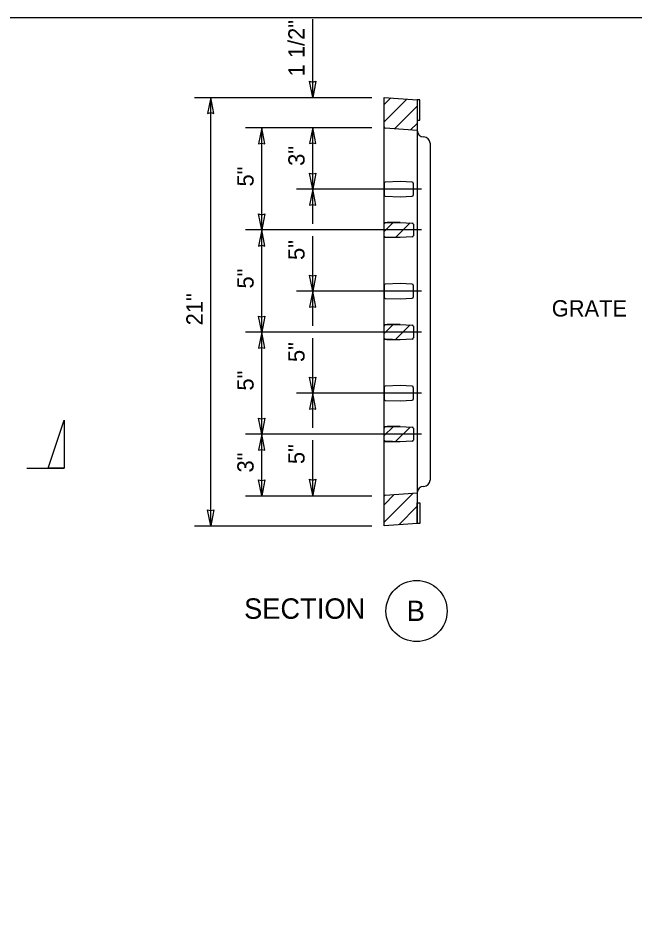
# Model space of a CAD drawing. Extents: x 99862 to 103151, y 100000 to 102076.
# Drawn here: x 100524 to 101128, y 101197 to 102076 of the extents above; entities that cross this region are included whole.
import ezdxf

# ---------------------------------------------------------------- set-up
doc = ezdxf.new("R2010")
doc.units = 0
for name, color, linetype in [('Level 1', 7, 'Continuous'), ('Level 11', 7, 'Continuous'), ('Level 15', 7, 'Continuous'), ('Level 17', 7, 'Continuous'), ('Level 2', 7, 'Continuous'), ('Level 20', 7, 'Continuous'), ('Level 9', 7, 'Continuous')]:
    doc.layers.add(name, color=color, linetype=linetype)

msp = doc.modelspace()

# ---------------------------------------------------------------- linework, layer by layer
at = {"layer": 'Level 1'}
for p, q in [((100882.87, 101606.72), (100882.87, 101968.65)), ((100927.87, 101952.68), (100927.87, 101622.68))]:
    msp.add_line(p, q, dxfattribs=at)
msp.add_lwpolyline([(99862, 99999.5), (103151, 99999.5), (103151, 102075.5), (99862, 102075.5)], close=True, dxfattribs=at)
for centre, start, end in [((100921.62, 101965.18), 180, 270), ((100921.62, 101952.68), 0, 90), ((100921.62, 101622.68), 270, 0), ((100921.62, 101610.18), 90, 180)]:
    msp.add_arc(centre, 6.25, start, end, dxfattribs=at)
at = {"layer": 'Level 11'}
for points in [[(100917.87, 101995.18), (100915.37, 101995.18), (100915.37, 101975.18), (100917.87, 101975.18)], [(100917.87, 101580.18), (100915.37, 101580.18), (100915.37, 101600.18), (100917.87, 101600.18)]]:
    msp.add_lwpolyline(points, close=True, dxfattribs=at)
at = {"layer": 'Level 15'}
for p, q in [((100812.87, 101997.68), (100812.87, 102074.17)), ((100696.87, 101997.68), (100870.87, 101997.68)), ((100712.87, 101577.68), (100712.87, 101997.68)), ((100746.87, 101968.17), (100870.87, 101968.17)), ((100762.87, 101867.69), (100762.87, 101967.68)), ((100812.87, 101907.69), (100812.87, 101968.17)), ((100919.52, 101907.69), (100796.87, 101907.69)), ((100812.87, 101873.69), (100812.87, 101907.69)), ((100919.52, 101867.69), (100746.87, 101867.69)), ((100762.87, 101767.69), (100762.87, 101867.69)), ((100812.87, 101807.69), (100812.87, 101861.69)), ((100919.52, 101807.69), (100796.87, 101807.69)), ((100812.87, 101773.69), (100812.87, 101807.69)), ((100919.52, 101767.69), (100746.87, 101767.69)), ((100762.87, 101667.69), (100762.87, 101767.69)), ((100812.87, 101707.69), (100812.87, 101761.69)), ((100919.52, 101707.69), (100796.87, 101707.69)), ((100812.87, 101673.69), (100812.87, 101707.69)), ((100919.52, 101667.69), (100746.87, 101667.69)), ((100762.87, 101607.21), (100762.87, 101667.69)), ((100812.87, 101607.69), (100812.87, 101661.69)), ((100746.87, 101607.21), (100870.87, 101607.21)), ((100696.87, 101577.68), (100870.87, 101577.68))]:
    msp.add_line(p, q, dxfattribs=at)
for points in [[(100812.87, 101997.68), (100809.78, 102013.41), (100812.87, 102012.68), (100815.95, 102013.41)], [(100712.87, 101997.68), (100709.78, 101981.96), (100712.87, 101982.69), (100715.95, 101981.96)], [(100762.87, 101967.68), (100759.78, 101951.96), (100762.87, 101952.69), (100765.95, 101951.96)], [(100812.87, 101968.17), (100809.78, 101952.44), (100812.87, 101953.17), (100815.95, 101952.44)], [(100812.87, 101907.69), (100809.78, 101923.41), (100812.87, 101922.68), (100815.95, 101923.41)], [(100812.87, 101907.69), (100809.78, 101891.96), (100812.87, 101892.69), (100815.95, 101891.96)], [(100762.87, 101867.69), (100759.78, 101883.41), (100762.87, 101882.68), (100765.95, 101883.41)], [(100762.87, 101867.69), (100759.78, 101851.96), (100762.87, 101852.69), (100765.95, 101851.96)], [(100812.87, 101807.69), (100809.78, 101823.41), (100812.87, 101822.68), (100815.95, 101823.41)], [(100812.87, 101807.69), (100809.78, 101791.96), (100812.87, 101792.69), (100815.95, 101791.96)], [(100762.87, 101767.69), (100759.78, 101783.41), (100762.87, 101782.68), (100765.95, 101783.41)], [(100762.87, 101767.69), (100759.78, 101751.96), (100762.87, 101752.69), (100765.95, 101751.96)], [(100812.87, 101707.69), (100809.78, 101723.41), (100812.87, 101722.68), (100815.95, 101723.41)], [(100812.87, 101707.69), (100809.78, 101691.96), (100812.87, 101692.69), (100815.95, 101691.96)], [(100762.87, 101667.69), (100759.78, 101683.41), (100762.87, 101682.68), (100765.95, 101683.41)], [(100762.87, 101667.69), (100759.78, 101651.96), (100762.87, 101652.69), (100765.95, 101651.96)], [(100762.87, 101607.21), (100759.78, 101622.93), (100762.87, 101622.2), (100765.95, 101622.93)], [(100812.87, 101607.69), (100809.78, 101623.41), (100812.87, 101622.68), (100815.95, 101623.41)], [(100712.87, 101577.68), (100709.78, 101593.41), (100712.87, 101592.68), (100715.95, 101593.41)]]:
    msp.add_lwpolyline(points, close=True, dxfattribs=at)
at = {"layer": 'Level 17'}
for p, q in [((100882.87, 101990.61), (100889.44, 101997.18)), ((100882.87, 101973.64), (100905.19, 101995.97)), ((100893.1, 101966.9), (100915.37, 101989.17)), ((100908.85, 101965.69), (100915.37, 101972.2)), ((100882.87, 101866.19), (100891.61, 101874.93)), ((100894, 101860.35), (100908.29, 101874.64)), ((100882.87, 101766.19), (100891.61, 101774.93)), ((100894, 101760.35), (100908.29, 101774.64)), ((100882.87, 101666.19), (100891.61, 101674.93)), ((100894, 101660.35), (100908.29, 101674.64)), ((100882.87, 101581.48), (100911.25, 101609.87)), ((100882.87, 101598.45), (100892.87, 101608.45)), ((100882.99, 101607.06), (100883.62, 101607.69)), ((100897.14, 101578.78), (100915.37, 101597.01))]:
    msp.add_line(p, q, dxfattribs=at)
at = {"layer": 'Level 2'}
for p, q in [((100915.37, 101965.18), (100915.37, 101610.18)), ((100898.73, 101875.18), (100885.95, 101875.18)), ((100898.73, 101860.18), (100885.95, 101860.18)), ((100898.73, 101775.18), (100885.95, 101775.18)), ((100898.73, 101760.18), (100885.95, 101760.18)), ((100898.73, 101675.18), (100885.95, 101675.18)), ((100898.73, 101660.18), (100885.95, 101660.18))]:
    msp.add_line(p, q, dxfattribs=at)
for points in [[(100882.87, 101968.65), (100882.87, 101997.68), (100915.37, 101995.18), (100915.37, 101965.18), (100883.83, 101967.61)], [(100882.87, 101913.61), (100882.87, 101901.76)], [(100910.53, 101914.52), (100898.73, 101915.18), (100883.87, 101914.65)], [(100911.52, 101901.89), (100911.52, 101913.48)], [(100883.87, 101900.72), (100898.73, 101900.18), (100910.53, 101900.85)], [(100882.87, 101861.76), (100882.87, 101873.61)], [(100883.87, 101874.65), (100898.73, 101875.18), (100910.53, 101874.52)], [(100911.52, 101873.48), (100911.52, 101861.89)], [(100910.53, 101860.85), (100898.73, 101860.18), (100883.87, 101860.72)], [(100882.87, 101813.61), (100882.87, 101801.76)], [(100910.53, 101814.52), (100898.73, 101815.18), (100883.87, 101814.65)], [(100911.52, 101801.89), (100911.52, 101813.48)], [(100883.87, 101800.72), (100898.73, 101800.18), (100910.53, 101800.85)], [(100882.87, 101761.76), (100882.87, 101773.61)], [(100883.87, 101774.65), (100898.73, 101775.18), (100910.53, 101774.52)], [(100911.52, 101773.48), (100911.52, 101761.89)], [(100910.53, 101760.85), (100898.73, 101760.18), (100883.87, 101760.72)], [(100882.87, 101713.61), (100882.87, 101701.76)], [(100910.53, 101714.52), (100898.73, 101715.18), (100883.87, 101714.65)], [(100911.52, 101701.89), (100911.52, 101713.48)], [(100883.87, 101700.72), (100898.73, 101700.18), (100910.53, 101700.85)], [(100882.87, 101661.76), (100882.87, 101673.61)], [(100883.87, 101674.65), (100898.73, 101675.18), (100910.53, 101674.52)], [(100911.52, 101673.48), (100911.52, 101661.89)], [(100910.53, 101660.85), (100898.73, 101660.18), (100883.87, 101660.72)], [(100883.83, 101607.76), (100915.37, 101610.18), (100915.37, 101580.18), (100882.87, 101577.68), (100882.87, 101606.72)]]:
    msp.add_lwpolyline(points, dxfattribs=at)
for centre, start, end in [((100883.91, 101968.65), 180, 265.60129), ((100883.91, 101913.61), 92.05217, 180), ((100910.47, 101913.48), 360, 86.75804), ((100883.91, 101901.76), 180, 267.94783), ((100910.47, 101901.89), 273.24196, 0), ((100883.91, 101873.61), 92.05217, 180), ((100910.47, 101873.48), 0, 86.75804), ((100883.91, 101861.76), 180, 267.94783), ((100910.47, 101861.89), 273.24196, 0), ((100883.91, 101813.61), 92.05217, 180), ((100910.47, 101813.48), 360, 86.75804), ((100883.91, 101801.76), 180, 267.94783), ((100910.47, 101801.89), 273.24196, 0), ((100883.91, 101773.61), 92.05217, 180), ((100910.47, 101773.48), 0, 86.75804), ((100883.91, 101761.76), 180, 267.94783), ((100910.47, 101761.89), 273.24196, 0), ((100883.91, 101713.61), 92.05217, 180), ((100910.47, 101713.48), 360, 86.75804), ((100883.91, 101701.76), 180, 267.94783), ((100910.47, 101701.89), 273.24196, 0), ((100883.91, 101673.61), 92.05217, 180), ((100910.47, 101673.48), 0, 86.75804), ((100883.91, 101661.76), 180, 267.94783), ((100910.47, 101661.89), 273.24196, 0), ((100883.91, 101606.72), 94.39871, 180)]:
    msp.add_arc(centre, 1.04, start, end, dxfattribs=at)
for centre, major_axis, start_param, end_param in [((100885.37, 101875.27), (-2.5, -0.09), 6.281555, 8.088001), ((100885.37, 101860.1), (2.5, -0.09), 1.336777, 3.143223), ((100885.37, 101775.27), (-2.5, -0.09), 6.281555, 8.088001), ((100885.37, 101760.1), (2.5, -0.09), 1.336777, 3.143223), ((100885.37, 101675.27), (-2.5, -0.09), 6.281555, 8.088001), ((100885.37, 101660.1), (2.5, -0.09), 1.336777, 3.143223)]:
    msp.add_ellipse(centre, major_axis=major_axis, ratio=0.045396, start_param=start_param, end_param=end_param, dxfattribs=at)
at = {"layer": 'Level 9'}
msp.add_line((100532.51, 101634.4), (100569.03, 101634.4), dxfattribs=at)
msp.add_lwpolyline([(100553.51, 101634.4), (100569.04, 101681.28), (100569.04, 101634.4)], close=True, dxfattribs=at)
msp.add_circle((100914.68, 101494.34), 30, dxfattribs=at)

# ---------------------------------------------------------------- texts
at = {"layer": 'Level 20'}
for s, p in [('1 1/2"', (100804.87, 102018.25)), ('3"', (100804.87, 101930.56)), ('5"', (100754.87, 101910.32)), ('5"', (100804.87, 101838.32)), ('5"', (100754.87, 101810.32)), ('21"', (100704.87, 101774.28)), ('5"', (100804.87, 101738.32)), ('5"', (100754.87, 101710.32)), ('5"', (100804.87, 101638.32)), ('3"', (100754.87, 101630.08))]:
    msp.add_text(s, height=16, rotation=90, dxfattribs=at).set_placement(p)
for s, height, p in [('GRATE', 16, (101047.32, 101782.92)), ('SECTION', 20, (100745.49, 101486.72)), ('B', 20, (100905.03, 101484.52))]:
    msp.add_text(s, height=height, dxfattribs=at).set_placement(p)

doc.saveas('drawing.dxf')
